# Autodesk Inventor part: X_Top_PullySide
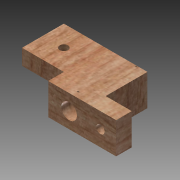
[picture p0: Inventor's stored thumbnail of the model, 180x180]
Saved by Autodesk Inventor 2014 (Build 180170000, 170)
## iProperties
Created: 2013-12
Part Number: X_Top_PullySide
Material: Birch
Document SubType Name: Modeling
Designer: Bram
Density: 0.512 g/cm^3
Appearance: Birch - Natural Medium Gloss
Author: Bram
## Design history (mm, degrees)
sketch "Sketch1"
  geometry: L1 (0, 0)-(105, 0); L2 (105, 0)-(105, 30); L3 (105, 30)-(0, 30); L4 (0, 30)-(0, 0); L5 (105, 0)-(65, 0); L6 (65, 0)-(65, 15); L7 (65, 15)-(105, 15); L8 (105, 15)-(105, 0); C1 r 4 at (15, 15); C2 r 7.5 at (45, 15)
  constraints: 16 end point, 4 parallel, 2 centre point, 2 horizontal, 2 perpendicular
  dimensions: "d0" = 105 distance of L3.end L2.end; "d1" = 30 distance of L2.end L1.end; "d2" = 40 distance of L6.end L7.end; "d6" = 8 diameter of C1; "d7" = 15 diameter of C2
extrude "Extrusion1" new body sketch "Sketch1" distance "d8" = 55; taper "d9" = 0 deg
sketch "Sketch2"
  geometry: L1 (0, 55)-(25, 55); L2 (25, 55)-(25, 15); L3 (25, 15)-(0, 15); L4 (0, 15)-(0, 55)
  constraints: 8 end point, 2 parallel, 1 horizontal, 1 perpendicular
  dimensions: "d10" = 25 distance of L2.end L3.end; "d11" = 40 distance of L1.end L2.end
extrude "Extrusion2" cut sketch "Sketch2" distance "d12" = 55; taper "d13" = 0 deg
sketch "Sketch3"
  geometry: L1 (40, 0)-(0, 0); L2 (0, 0)-(0, 15); L3 (0, 15)-(40, 15); L4 (40, 15)-(40, 0); C1 r 4 at (20, 35); 1 further point
  constraints: 8 end point, 2 parallel, 1 centre point, 1 horizontal, 1 perpendicular
  dimensions: "d14" = 40 distance of L2.end L3.end; "d15" = 15 distance of L1.end L2.end; "d16" = 8 diameter of C1
extrude "Extrusion3" cut sketch "Sketch3" distance "d17" = 55; taper "d18" = 0 deg
body "Solid1"
